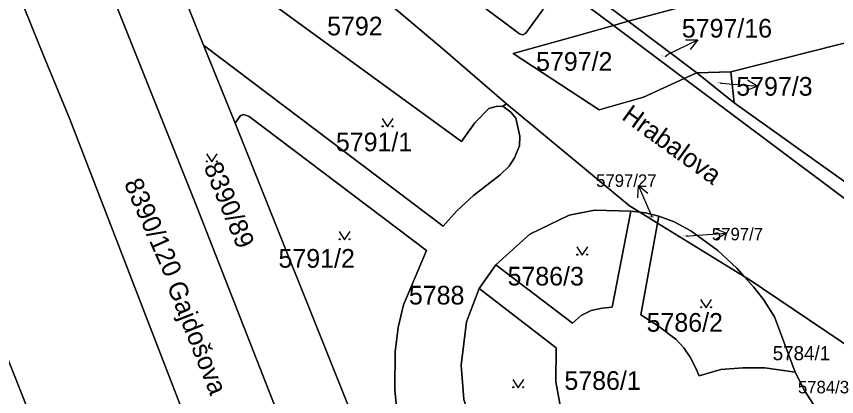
# Model space of a CAD drawing. Extents: x -596233 to -595156, y -1161235 to -1159375.
# Drawn here: x -595514 to -595439.3, y -1160351.8 to -1160317.2 of the extents above; entities that cross this region are included whole.
import ezdxf

# ---------------------------------------------------------------- set-up
doc = ezdxf.new("R2010")
doc.units = 0
for name, color, linetype in [('KN_KULTURY', 7, 'Continuous'), ('KN_PARC_CIS_POM', 7, 'Continuous'), ('KN_PARC_CIS_POZ', 7, 'Continuous'), ('KN_PARC_PLOCHA', 7, 'Continuous'), ('KN_ULICE', 7, 'Continuous'), ('PARC_C_SIPKA', 7, 'Continuous'), ('parcely_l', 7, 'Continuous')]:
    doc.layers.add(name, color=color, linetype=linetype)

msp = doc.modelspace()

# ---------------------------------------------------------------- linework, layer by layer
at = {"layer": 'KN_KULTURY'}
for points in [[(-595480.7018, -1160326.4616), (-595480.2018, -1160327.2116), (-595479.7018, -1160326.4616)], [(-595496.7218, -1160329.6516), (-595496.2218, -1160330.4016), (-595495.7218, -1160329.6516)], [(-595484.6218, -1160336.7416), (-595484.1218, -1160337.4916), (-595483.6218, -1160336.7416)], [(-595462.9718, -1160338.1416), (-595462.4718, -1160338.8916), (-595461.9718, -1160338.1416)], [(-595451.6918, -1160342.9316), (-595451.1918, -1160343.6816), (-595450.6918, -1160342.9316)], [(-595468.8018, -1160350.2116), (-595468.3018, -1160350.9616), (-595467.8018, -1160350.2116)]]:
    msp.add_lwpolyline(points, dxfattribs=at)
for centre in [(-595480.652, -1160327.1614), (-595479.7526, -1160327.1614), (-595496.672, -1160330.3514), (-595495.7726, -1160330.3514), (-595484.572, -1160337.4414), (-595483.6726, -1160337.4414), (-595462.922, -1160338.8414), (-595462.0226, -1160338.8414), (-595451.642, -1160343.6314), (-595450.7426, -1160343.6314), (-595468.752, -1160350.9114), (-595467.8526, -1160350.9114)]:
    msp.add_circle(centre, 0.05, dxfattribs=at)
at = {"layer": 'KN_PARC_PLOCHA'}
for points in [[(-595384.36, -1160297.87), (-595421.13, -1160307.68), (-595458.28, -1160317.6), (-595463.57, -1160313.65), (-595387.41, -1160291.12), (-595385.68, -1160294.81)], [(-595488.42, -1160357.8), (-595483.88, -1160369.22), (-595491.65, -1160371.85), (-595509.16, -1160326.51), (-595511.56, -1160320.72), (-595513.74, -1160315.29), (-595516.45, -1160308.75), (-595518.49, -1160303.81), (-595522.09, -1160295.05), (-595514.28, -1160292.6), (-595509.38, -1160305.03), (-595497.6, -1160334.5), (-595490.11, -1160353.55)], [(-595505.22, -1160298.13), (-595505.24, -1160299.15), (-595496.97, -1160319.76), (-595494.11, -1160326.88), (-595483.07, -1160354.4), (-595483.85, -1160353.15), (-595486.53, -1160354.45), (-595478.53, -1160367.41), (-595482.66, -1160368.81), (-595487.57, -1160359.24), (-595488.42, -1160357.8), (-595490.11, -1160353.55), (-595497.6, -1160334.5), (-595509.38, -1160305.03), (-595514.28, -1160292.6), (-595513.78, -1160292.19), (-595511.53, -1160293.52), (-595508.15, -1160295.89)], [(-595493.99, -1160306.09), (-595497.56, -1160311), (-595473.47, -1160328.54), (-595472.26, -1160326.83), (-595470.98, -1160325.55), (-595470.32, -1160325.36), (-595469.72, -1160325.32), (-595468.98, -1160325.86), (-595468.53, -1160326.42), (-595468.15, -1160328.04), (-595468.19, -1160328.93), (-595468.64, -1160330.04), (-595469.14, -1160330.8), (-595469.95, -1160331.58), (-595472.37, -1160333.47), (-595473.89, -1160334.84), (-595475.14, -1160336.25), (-595496.97, -1160319.76), (-595505.24, -1160299.15), (-595505.22, -1160298.13), (-595504.44, -1160298.73), (-595497.26, -1160303.51)], [(-595469.38, -1160325.12), (-595469.72, -1160325.32), (-595470.32, -1160325.36), (-595470.98, -1160325.55), (-595472.26, -1160326.83), (-595473.47, -1160328.54), (-595497.56, -1160311), (-595493.99, -1160306.09), (-595492.55, -1160307.23), (-595489.34, -1160308.91), (-595486.24, -1160311.28), (-595480.37, -1160315.72), (-595475.13, -1160320.14)], [(-595419.2, -1160314.39), (-595427.2, -1160316.68), (-595436.7, -1160319.09), (-595448.93, -1160322.19), (-595452.03, -1160322.28), (-595458.28, -1160317.6), (-595421.13, -1160307.68)], [(-595458.28, -1160317.6), (-595459.63, -1160317.98), (-595464.48, -1160314.35), (-595467.6, -1160318.68), (-595467.89, -1160318.83), (-595468.2, -1160318.73), (-595471.8, -1160316.05), (-595467.76, -1160314.87), (-595463.57, -1160313.65)], [(-595418.2, -1160347.25), (-595431.66, -1160337.39), (-595431.97, -1160336.89), (-595448.64, -1160325.02), (-595448.93, -1160322.19), (-595436.7, -1160319.09), (-595427.2, -1160316.68), (-595426.62, -1160318.48)], [(-595453.17, -1160322.81), (-595456.88, -1160324.51), (-595460.92, -1160325.66), (-595468.76, -1160320.52), (-595462.98, -1160318.91), (-595459.63, -1160317.98)], [(-595452.03, -1160322.28), (-595453.17, -1160322.81), (-595459.63, -1160317.98), (-595458.28, -1160317.6)], [(-595448.64, -1160325.02), (-595431.97, -1160336.89), (-595431.66, -1160337.39), (-595418.2, -1160347.25), (-595409.44, -1160353.77), (-595411.48, -1160354.35), (-595411.79, -1160354.2), (-595413.13, -1160352.75), (-595453.17, -1160322.81), (-595452.03, -1160322.28)], [(-595448.64, -1160325.02), (-595452.03, -1160322.28), (-595448.93, -1160322.19)], [(-595474.32, -1160365.99), (-595475.58, -1160366.42), (-595483.07, -1160354.4), (-595494.11, -1160326.88), (-595493.61, -1160326.17), (-595493.31, -1160326.08), (-595492.83, -1160326.25), (-595476.66, -1160338.45), (-595478.75, -1160343.4), (-595479.23, -1160345.46), (-595479.53, -1160347.69), (-595479.55, -1160351.13), (-595479.4, -1160352.75), (-595478.96, -1160354.38)], [(-595458.04, -1160334.87), (-595459.75, -1160343.63), (-595460.67, -1160343.7), (-595461.65, -1160343.92), (-595462.56, -1160344.38), (-595463.37, -1160345.07), (-595470.35, -1160339.78), (-595467.25, -1160336.99), (-595463.66, -1160335.25), (-595461.37, -1160334.8)], [(-595455.49, -1160335.35), (-595455.6, -1160335.97), (-595457.23, -1160334.97), (-595456.72, -1160335.04)], [(-595447.72, -1160340.82), (-595455.6, -1160335.97), (-595455.49, -1160335.35), (-595454.09, -1160335.85), (-595452.59, -1160336.67), (-595450.11, -1160338.45), (-595448.38, -1160340.06)], [(-595447.72, -1160340.82), (-595446.88, -1160341.77), (-595445.97, -1160342.93), (-595444.95, -1160344.5), (-595443.07, -1160349.54), (-595445.84, -1160349.16), (-595447.85, -1160349.14), (-595449.85, -1160349.31), (-595451.81, -1160349.88), (-595452.17, -1160349.04), (-595452.63, -1160348.17), (-595453.21, -1160347.32), (-595453.91, -1160346.58), (-595455.51, -1160345.35), (-595457.14, -1160344.31), (-595455.6, -1160335.97)], [(-595431.71, -1160351.57), (-595432.2, -1160351.74), (-595435.05, -1160349.61), (-595435.99, -1160349.62), (-595436.81, -1160350.49), (-595436.95, -1160351.22), (-595436.74, -1160351.94), (-595436.59, -1160351.95), (-595436.27, -1160353.11), (-595440.16, -1160354.43), (-595442.22, -1160351.2), (-595443.07, -1160349.54), (-595444.95, -1160344.5), (-595445.97, -1160342.93), (-595446.88, -1160341.77), (-595447.72, -1160340.82), (-595447.45, -1160340.98)], [(-595465.24, -1160362.91), (-595468.7, -1160364.09), (-595472.38, -1160354.8), (-595473.26, -1160352.03), (-595473.51, -1160348.91), (-595473.02, -1160344.96), (-595471.85, -1160341.93), (-595464.85, -1160347.33), (-595464.88, -1160350.43), (-595464.51, -1160352.4), (-595463.35, -1160356.24), (-595463.2, -1160357.24), (-595463.26, -1160358.22), (-595464.19, -1160360.02), (-595464.95, -1160361.86)]]:
    msp.add_lwpolyline(points, close=True, dxfattribs=at)
for points in [[(-595516.45, -1160308.75), (-595513.74, -1160315.29), (-595511.56, -1160320.72), (-595509.16, -1160326.51), (-595491.65, -1160371.85), (-595489.02, -1160378.2), (-595482.37, -1160394.93), (-595480.37, -1160400.59), (-595473.92, -1160417.66), (-595471.36, -1160424.09), (-595463.86, -1160442.98), (-595475.37, -1160447.79), (-595483.26, -1160428), (-595484.78, -1160424.75), (-595493.72, -1160401.6), (-595495.44, -1160397.2), (-595497.53, -1160392.05), (-595510.34, -1160359.58), (-595514.98, -1160347.86)], [(-595471.8, -1160316.05), (-595468.2, -1160318.73), (-595467.89, -1160318.83), (-595467.6, -1160318.68), (-595464.48, -1160314.35), (-595459.63, -1160317.98), (-595462.98, -1160318.91), (-595468.76, -1160320.52), (-595460.92, -1160325.66), (-595456.88, -1160324.51), (-595453.17, -1160322.81), (-595413.13, -1160352.75)], [(-595431.71, -1160351.57), (-595447.45, -1160340.98), (-595447.72, -1160340.82), (-595448.38, -1160340.06), (-595450.11, -1160338.45), (-595452.59, -1160336.67), (-595454.09, -1160335.85), (-595455.49, -1160335.35), (-595456.72, -1160335.04), (-595457.23, -1160334.97), (-595458.18, -1160334.39), (-595469.38, -1160325.12), (-595475.13, -1160320.14), (-595480.37, -1160315.72)], [(-595479.4, -1160352.75), (-595479.55, -1160351.13), (-595479.53, -1160347.69), (-595479.23, -1160345.46), (-595478.75, -1160343.4), (-595476.66, -1160338.45), (-595492.83, -1160326.25), (-595493.31, -1160326.08), (-595493.61, -1160326.17), (-595494.11, -1160326.88), (-595496.97, -1160319.76), (-595475.14, -1160336.25), (-595473.89, -1160334.84), (-595472.37, -1160333.47), (-595469.95, -1160331.58), (-595469.14, -1160330.8), (-595468.64, -1160330.04), (-595468.19, -1160328.93), (-595468.15, -1160328.04), (-595468.53, -1160326.42), (-595468.98, -1160325.86), (-595469.72, -1160325.32), (-595469.38, -1160325.12), (-595458.18, -1160334.39), (-595457.23, -1160334.97), (-595458.04, -1160334.87), (-595461.37, -1160334.8), (-595463.66, -1160335.25), (-595467.25, -1160336.99), (-595470.35, -1160339.78), (-595471.85, -1160341.93), (-595473.02, -1160344.96), (-595473.51, -1160348.91), (-595473.26, -1160352.03)], [(-595464.51, -1160352.4), (-595464.88, -1160350.43), (-595464.85, -1160347.33), (-595471.85, -1160341.93), (-595470.35, -1160339.78), (-595463.37, -1160345.07), (-595462.56, -1160344.38), (-595461.65, -1160343.92), (-595460.67, -1160343.7), (-595459.75, -1160343.63), (-595458.04, -1160334.87), (-595457.23, -1160334.97), (-595455.6, -1160335.97), (-595457.14, -1160344.31), (-595455.51, -1160345.35), (-595453.91, -1160346.58), (-595453.21, -1160347.32), (-595452.63, -1160348.17), (-595452.17, -1160349.04), (-595451.81, -1160349.88), (-595449.85, -1160349.31), (-595447.85, -1160349.14), (-595445.84, -1160349.16), (-595443.07, -1160349.54), (-595442.22, -1160351.2), (-595440.16, -1160354.43)], [(-595514.98, -1160347.86), (-595510.34, -1160359.58), (-595497.53, -1160392.05), (-595495.44, -1160397.2), (-595493.72, -1160401.6), (-595484.78, -1160424.75), (-595483.26, -1160428), (-595475.37, -1160447.79), (-595477.33, -1160448.61), (-595480.11, -1160449.77), (-595483.73, -1160440.75), (-595485.65, -1160435.91), (-595492.34, -1160419.07), (-595495.94, -1160409.83), (-595504.35, -1160388.43), (-595506.07, -1160384.36), (-595513.26, -1160365.9), (-595516.77, -1160357.02)]]:
    msp.add_lwpolyline(points, dxfattribs=at)
at = {"layer": 'PARC_C_SIPKA'}
for points in [[(-595454.93, -1160320.79), (-595454.65, -1160320.6), (-595451.9488, -1160319.2947)], [(-595453.0668, -1160319.2796), (-595451.9488, -1160319.2947), (-595452.6317, -1160320.18)], [(-595449.87, -1160323.23), (-595449.46, -1160323.26), (-595446.4687, -1160323.4887)], [(-595447.4277, -1160322.914), (-595446.4687, -1160323.4887), (-595447.5039, -1160323.911)], [(-595457.4162, -1160333.6554), (-595457.3565, -1160332.5389), (-595456.4992, -1160333.2565)], [(-595456.09, -1160335.46), (-595456.16, -1160335.29), (-595457.3565, -1160332.5389)], [(-595452.99, -1160337.16), (-595452.33, -1160337.11), (-595449.3394, -1160336.8724)], [(-595450.3759, -1160336.4532), (-595449.3394, -1160336.8724), (-595450.2967, -1160337.45)]]:
    msp.add_lwpolyline(points, dxfattribs=at)
at = {"layer": 'parcely_l'}
for points in [[(-595475.37, -1160447.79), (-595483.26, -1160428), (-595484.78, -1160424.75), (-595493.72, -1160401.6), (-595495.44, -1160397.2), (-595497.53, -1160392.05), (-595510.34, -1160359.58), (-595514.98, -1160347.86), (-595515.95, -1160345.24), (-595520.05, -1160335.27), (-595522.38, -1160329.79), (-595526.04, -1160320.13), (-595529.79, -1160310.64), (-595530.84, -1160308.18), (-595535.89, -1160295.48), (-595538.65, -1160292), (-595541.32, -1160290.37), (-595543.78, -1160289.37)], [(-595488.42, -1160357.8), (-595490.11, -1160353.55), (-595497.6, -1160334.5), (-595509.38, -1160305.03), (-595514.28, -1160292.6)], [(-595522.09, -1160295.05), (-595518.49, -1160303.81), (-595516.45, -1160308.75), (-595513.74, -1160315.29), (-595511.56, -1160320.72), (-595509.16, -1160326.51), (-595491.65, -1160371.85)], [(-595496.97, -1160319.76), (-595505.24, -1160299.15), (-595505.22, -1160298.13)], [(-595493.99, -1160306.09), (-595497.56, -1160311), (-595473.47, -1160328.54), (-595472.26, -1160326.83), (-595470.98, -1160325.55), (-595470.32, -1160325.36), (-595469.72, -1160325.32)], [(-595469.38, -1160325.12), (-595475.13, -1160320.14), (-595480.37, -1160315.72), (-595486.24, -1160311.28), (-595489.34, -1160308.91), (-595492.55, -1160307.23), (-595493.99, -1160306.09)], [(-595421.13, -1160307.68), (-595458.28, -1160317.6)], [(-595458.28, -1160317.6), (-595463.57, -1160313.65)], [(-595471.8, -1160316.05), (-595468.2, -1160318.73), (-595467.89, -1160318.83), (-595467.6, -1160318.68), (-595464.48, -1160314.35), (-595459.63, -1160317.98)], [(-595427.2, -1160316.68), (-595436.7, -1160319.09), (-595448.93, -1160322.19)], [(-595459.63, -1160317.98), (-595462.98, -1160318.91), (-595468.76, -1160320.52), (-595460.92, -1160325.66), (-595456.88, -1160324.51), (-595453.17, -1160322.81)], [(-595459.63, -1160317.98), (-595458.28, -1160317.6)], [(-595453.17, -1160322.81), (-595459.63, -1160317.98)], [(-595452.03, -1160322.28), (-595458.28, -1160317.6)], [(-595469.72, -1160325.32), (-595468.98, -1160325.86), (-595468.53, -1160326.42), (-595468.15, -1160328.04), (-595468.19, -1160328.93), (-595468.64, -1160330.04), (-595469.14, -1160330.8), (-595469.95, -1160331.58), (-595472.37, -1160333.47), (-595473.89, -1160334.84), (-595475.14, -1160336.25), (-595496.97, -1160319.76)], [(-595496.97, -1160319.76), (-595494.11, -1160326.88)], [(-595452.03, -1160322.28), (-595453.17, -1160322.81)], [(-595453.17, -1160322.81), (-595413.13, -1160352.75), (-595411.79, -1160354.2), (-595411.48, -1160354.35)], [(-595448.93, -1160322.19), (-595452.03, -1160322.28)], [(-595448.64, -1160325.02), (-595452.03, -1160322.28)], [(-595448.64, -1160325.02), (-595448.93, -1160322.19)], [(-595418.2, -1160347.25), (-595431.66, -1160337.39), (-595431.97, -1160336.89), (-595448.64, -1160325.02)], [(-595469.38, -1160325.12), (-595469.72, -1160325.32)], [(-595457.23, -1160334.97), (-595458.18, -1160334.39), (-595469.38, -1160325.12)], [(-595474.32, -1160365.99), (-595478.96, -1160354.38), (-595479.4, -1160352.75), (-595479.55, -1160351.13), (-595479.53, -1160347.69), (-595479.23, -1160345.46), (-595478.75, -1160343.4), (-595476.66, -1160338.45), (-595492.83, -1160326.25), (-595493.31, -1160326.08), (-595493.61, -1160326.17), (-595494.11, -1160326.88)], [(-595494.11, -1160326.88), (-595483.07, -1160354.4)], [(-595470.35, -1160339.78), (-595467.25, -1160336.99), (-595463.66, -1160335.25), (-595461.37, -1160334.8), (-595458.04, -1160334.87)], [(-595470.35, -1160339.78), (-595463.37, -1160345.07), (-595462.56, -1160344.38), (-595461.65, -1160343.92), (-595460.67, -1160343.7), (-595459.75, -1160343.63), (-595458.04, -1160334.87)], [(-595458.04, -1160334.87), (-595457.23, -1160334.97)], [(-595455.49, -1160335.35), (-595456.72, -1160335.04), (-595457.23, -1160334.97)], [(-595455.6, -1160335.97), (-595457.23, -1160334.97)], [(-595455.6, -1160335.97), (-595455.49, -1160335.35)], [(-595447.72, -1160340.82), (-595448.38, -1160340.06), (-595450.11, -1160338.45), (-595452.59, -1160336.67), (-595454.09, -1160335.85), (-595455.49, -1160335.35)], [(-595443.07, -1160349.54), (-595445.84, -1160349.16), (-595447.85, -1160349.14), (-595449.85, -1160349.31), (-595451.81, -1160349.88), (-595452.17, -1160349.04), (-595452.63, -1160348.17), (-595453.21, -1160347.32), (-595453.91, -1160346.58), (-595455.51, -1160345.35), (-595457.14, -1160344.31), (-595455.6, -1160335.97)], [(-595455.6, -1160335.97), (-595447.72, -1160340.82)], [(-595471.85, -1160341.93), (-595470.35, -1160339.78)], [(-595431.71, -1160351.57), (-595447.45, -1160340.98), (-595447.72, -1160340.82)], [(-595443.07, -1160349.54), (-595444.95, -1160344.5), (-595445.97, -1160342.93), (-595446.88, -1160341.77), (-595447.72, -1160340.82)], [(-595471.85, -1160341.93), (-595473.02, -1160344.96), (-595473.51, -1160348.91), (-595473.26, -1160352.03), (-595472.38, -1160354.8), (-595468.7, -1160364.09)], [(-595465.24, -1160362.91), (-595464.95, -1160361.86), (-595464.19, -1160360.02), (-595463.26, -1160358.22), (-595463.2, -1160357.24), (-595463.35, -1160356.24), (-595464.51, -1160352.4), (-595464.88, -1160350.43), (-595464.85, -1160347.33), (-595471.85, -1160341.93)], [(-595440.16, -1160354.43), (-595442.22, -1160351.2), (-595443.07, -1160349.54)]]:
    msp.add_lwpolyline(points, dxfattribs=at)

# ---------------------------------------------------------------- texts
at = {"layer": 'KN_PARC_CIS_POM'}
for s, p in [('5797/16', (-595455.2633, -1160320.79)), ('5797/3', (-595450.1533, -1160323.23)), ('5797/27', (-595456.4233, -1160335.46)), ('5797/7', (-595453.2733, -1160337.16))]:
    msp.add_text(s, height=0.1, dxfattribs=at).set_placement(p)
at = {"layer": 'KN_PARC_CIS_POZ'}
for s, height, p in [('5792', 1.7, (-595485.7166, -1160318.88)), ('5797/16', 1.7, (-595453.3966, -1160319.08)), ('5797/2', 1.7, (-595466.6766, -1160322.1)), ('5797/3', 1.7, (-595448.4366, -1160324.37)), ('5791/1', 1.7, (-595484.9166, -1160329.43)), ('5797/27', 1.14, (-595461.21, -1160332.67)), ('5797/7', 1.14, (-595450.66, -1160337.54)), ('5791/2', 1.7, (-595490.1466, -1160340.03)), ('5786/3', 1.7, (-595469.2766, -1160341.65)), ('5788', 1.7, (-595478.2666, -1160343.38)), ('5786/2', 1.7, (-595456.6066, -1160345.86)), ('5784/1', 1.28, (-595445.1166, -1160348.45)), ('5786/1', 1.7, (-595464.0966, -1160351.15)), ('5784/3', 1.14, (-595442.82, -1160351.47))]:
    msp.add_text(s, height=height, dxfattribs=at).set_placement(p)
for s, rotation, p in [('8390/89', 292.562829, (-595496.9943, -1160330.8371)), ('8390/120', 293.769485, (-595504.2566, -1160332.3462))]:
    msp.add_text(s, height=1.7, rotation=rotation, dxfattribs=at).set_placement(p)
at = {"layer": 'KN_ULICE'}
for s, rotation, p in [('Hrabalova', 324.079232, (-595458.9757, -1160326.4583)), ('Gajdošova', 291.636601, (-595500.3463, -1160341.6558))]:
    msp.add_text(s, height=1.7, rotation=rotation, dxfattribs=at).set_placement(p)

doc.saveas('drawing.dxf')
